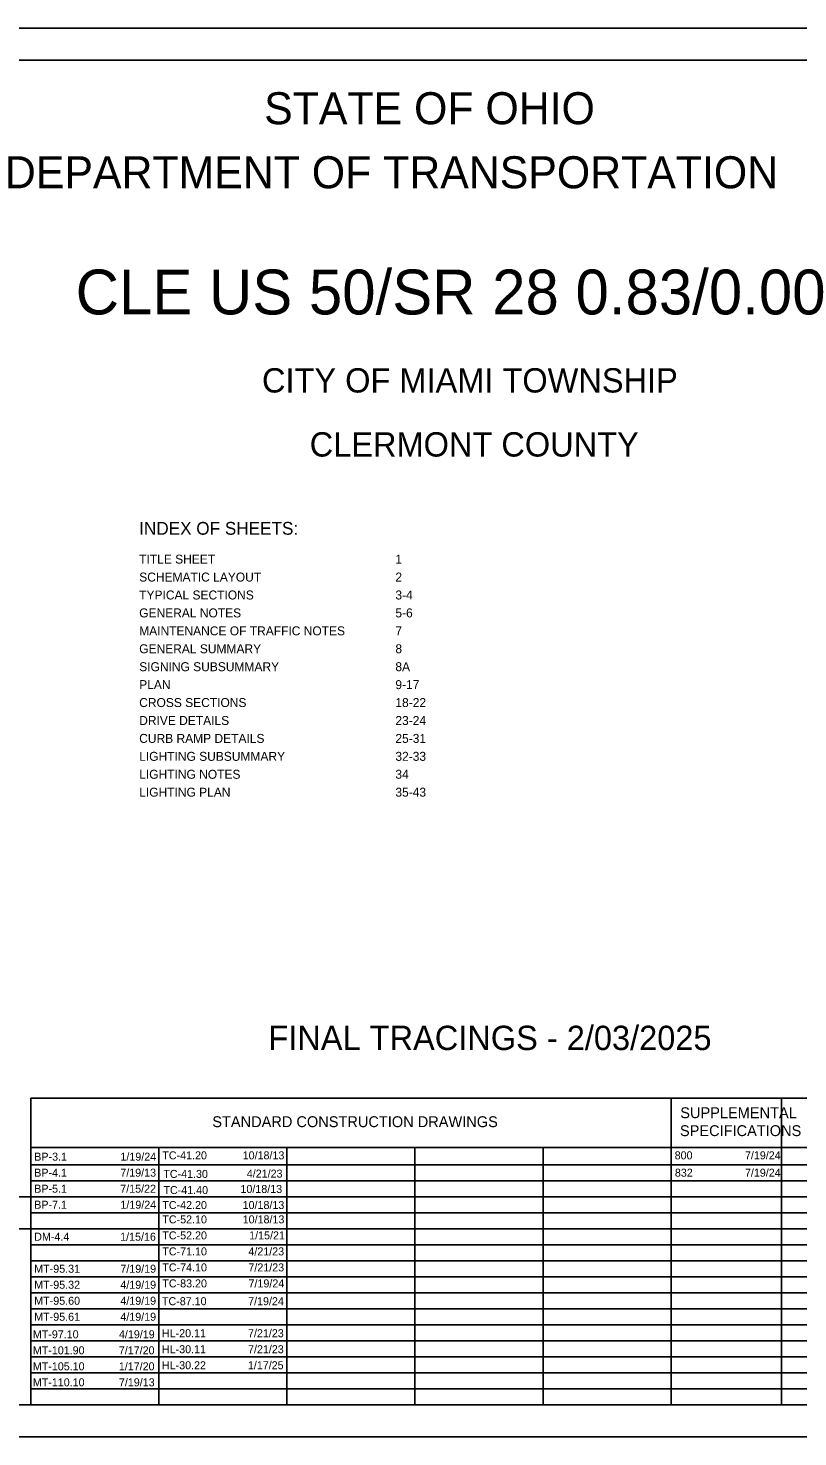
# Model space of a CAD drawing. Extents: x 44.2 to 78.2, y 4.5 to 26.5.
# Drawn here: x 54.35 to 66.36, y 4.5 to 26.5 of the extents above; entities that cross this region are included whole.
import ezdxf

# ---------------------------------------------------------------- set-up
doc = ezdxf.new("R2010")
doc.units = 0
for name, color, linetype in [('Default', 7, 'Continuous'), ('SH_Border', 7, 'Continuous'), ('SH_Cut_Line', 7, 'Continuous'), ('SH_Data', 7, 'Continuous'), ('SH_Text', 7, 'Continuous')]:
    doc.layers.add(name, color=color, linetype=linetype)

msp = doc.modelspace()

# ---------------------------------------------------------------- linework, layer by layer
at = {"layer": 'SH_Border'}
msp.add_lwpolyline([(45.736, 26.001), (77.736, 26.001), (77.736, 5.001), (45.736, 5.001)], close=True, dxfattribs=at)
at = {"layer": 'SH_Cut_Line'}
msp.add_lwpolyline([(44.236, 4.501), (78.236, 4.501), (78.236, 26.501), (44.236, 26.501)], close=True, dxfattribs=at)
at = {"layer": 'SH_Data'}
for p, q in [((54.386, 9.793), (67.836, 9.793)), ((54.386, 5.001), (54.386, 9.793)), ((64.386, 5.001), (64.386, 9.793)), ((66.111, 5.001), (66.111, 9.793)), ((54.386, 9.022), (67.836, 9.022)), ((56.386, 5.001), (56.386, 9.022)), ((58.386, 5.001), (58.386, 9.022)), ((60.386, 5.001), (60.386, 9.022)), ((62.386, 5.001), (62.386, 9.022)), ((54.386, 8.751), (67.836, 8.751)), ((54.386, 8.501), (67.836, 8.501)), ((51.586, 8.251), (54.386, 8.251)), ((54.386, 8.251), (67.836, 8.251)), ((54.386, 8.001), (67.836, 8.001)), ((51.586, 7.751), (54.386, 7.751)), ((54.386, 7.751), (67.836, 7.751)), ((54.386, 7.501), (67.836, 7.501)), ((54.386, 7.251), (67.836, 7.251)), ((54.386, 7.001), (67.836, 7.001)), ((54.386, 6.751), (67.836, 6.751)), ((54.386, 6.501), (67.836, 6.501)), ((54.386, 6.251), (67.836, 6.251)), ((54.386, 6.001), (67.836, 6.001)), ((54.386, 5.751), (67.836, 5.751)), ((54.386, 5.501), (67.836, 5.501)), ((54.386, 5.251), (67.836, 5.251))]:
    msp.add_line(p, q, dxfattribs=at)

# ---------------------------------------------------------------- texts
at = {"layer": 'Default'}
for s, p in [('BP-3.1', (54.441, 8.814)), ('1/19/24', (55.787, 8.814)), ('TC-41.20', (56.441, 8.835)), ('10/18/13', (57.696, 8.835)), ('800', (64.441, 8.835)), ('7/19/24', (65.538, 8.835)), ('BP-4.1', (54.441, 8.564)), ('7/19/13', (55.785, 8.564)), ('TC-41.30', (56.456, 8.545)), ('4/21/23', (57.76, 8.55)), ('832', (64.444, 8.564)), ('7/19/24', (65.538, 8.564)), ('BP-5.1', (54.441, 8.314)), ('7/15/22', (55.784, 8.314)), ('TC-41.40', (56.458, 8.293)), ('10/18/13', (57.661, 8.31)), ('BP-7.1', (54.441, 8.064)), ('1/19/24', (55.787, 8.064)), ('TC-42.20', (56.441, 8.059)), ('10/18/13', (57.695, 8.059)), ('TC-52.10', (56.441, 7.835)), ('10/18/13', (57.696, 7.835)), ('TC-52.20', (56.441, 7.585)), ('1/15/21', (57.797, 7.585)), ('DM-4.4', (54.441, 7.564)), ('1/15/16', (55.783, 7.564)), ('TC-71.10', (56.441, 7.335)), ('4/21/23', (57.785, 7.335)), ('MT-95.31', (54.441, 7.064)), ('7/19/19', (55.786, 7.064)), ('TC-74.10', (56.441, 7.085)), ('7/21/23', (57.785, 7.085)), ('MT-95.32', (54.441, 6.814)), ('4/19/19', (55.786, 6.814)), ('TC-83.20', (56.441, 6.835)), ('7/19/24', (57.787, 6.835)), ('MT-95.60', (54.441, 6.564)), ('4/19/19', (55.786, 6.564)), ('TC-87.10', (56.435, 6.557)), ('7/19/24', (57.781, 6.557)), ('MT-95.61', (54.441, 6.314)), ('4/19/19', (55.786, 6.314)), ('MT-97.10', (54.419, 6.04)), ('4/19/19', (55.764, 6.04)), ('HL-20.11', (56.435, 6.057)), ('7/21/23', (57.779, 6.057)), ('MT-101.90', (54.419, 5.79)), ('7/17/20', (55.762, 5.79)), ('HL-30.11', (56.435, 5.807)), ('7/21/23', (57.779, 5.807)), ('MT-105.10', (54.419, 5.54)), ('1/17/20', (55.762, 5.54)), ('HL-30.22', (56.435, 5.557)), ('1/17/25', (57.777, 5.557)), ('MT-110.10', (54.419, 5.29)), ('7/19/13', (55.763, 5.29))]:
    msp.add_text(s, height=0.125, dxfattribs=at).set_placement(p)
at = {"layer": 'SH_Data'}
for s, p in [('TITLE SHEET', (56.08, 18.139)), ('SCHEMATIC LAYOUT', (56.08, 17.859)), ('TYPICAL SECTIONS', (56.08, 17.579)), ('GENERAL NOTES', (56.08, 17.299)), ('MAINTENANCE OF TRAFFIC NOTES', (56.08, 17.019)), ('GENERAL SUMMARY', (56.08, 16.739)), ('SIGNING SUBSUMMARY', (56.08, 16.459)), ('PLAN', (56.08, 16.179)), ('CROSS SECTIONS', (56.08, 15.899)), ('DRIVE DETAILS', (56.08, 15.619)), ('CURB RAMP DETAILS', (56.08, 15.339)), ('LIGHTING SUBSUMMARY', (56.08, 15.059)), ('LIGHTING NOTES', (56.08, 14.779)), ('LIGHTING PLAN', (56.08, 14.499))]:
    msp.add_text(s, height=0.14, dxfattribs=at).set_placement(p)
at = {"layer": 'SH_Text'}
for s, height, p in [('STATE OF OHIO', 0.5, (58.031, 25.001)), ('DEPARTMENT OF TRANSPORTATION', 0.5, (53.983, 24.001)), ('CLE US 50/SR 28 0.83/0.00', 0.7, (55.088, 22.031)), ('CITY OF MIAMI TOWNSHIP', 0.38, (57.997, 20.811)), ('CLERMONT COUNTY', 0.38, (58.742, 19.811)), ('INDEX OF SHEETS:', 0.2, (56.08, 18.59)), ('1', 0.14, (60.08, 18.139)), ('2', 0.14, (60.08, 17.859)), ('3-4', 0.14, (60.08, 17.579)), ('5-6', 0.14, (60.08, 17.299)), ('7', 0.14, (60.08, 17.019)), ('8', 0.14, (60.08, 16.739)), ('8A', 0.14, (60.08, 16.459)), ('9-17', 0.14, (60.08, 16.179)), ('18-22', 0.14, (60.08, 15.899)), ('23-24', 0.14, (60.08, 15.619)), ('25-31', 0.14, (60.08, 15.339)), ('32-33', 0.14, (60.08, 15.059)), ('34', 0.14, (60.08, 14.779)), ('35-43', 0.14, (60.08, 14.499)), ('FINAL TRACINGS - 2/03/2025', 0.38, (58.097, 10.542)), ('STANDARD CONSTRUCTION DRAWINGS', 0.17, (57.221, 9.338)), ('SUPPLEMENTAL', 0.17, (64.528, 9.478)), ('SPECIFICATIONS', 0.17, (64.523, 9.198))]:
    msp.add_text(s, height=height, dxfattribs=at).set_placement(p)

doc.saveas('drawing.dxf')
